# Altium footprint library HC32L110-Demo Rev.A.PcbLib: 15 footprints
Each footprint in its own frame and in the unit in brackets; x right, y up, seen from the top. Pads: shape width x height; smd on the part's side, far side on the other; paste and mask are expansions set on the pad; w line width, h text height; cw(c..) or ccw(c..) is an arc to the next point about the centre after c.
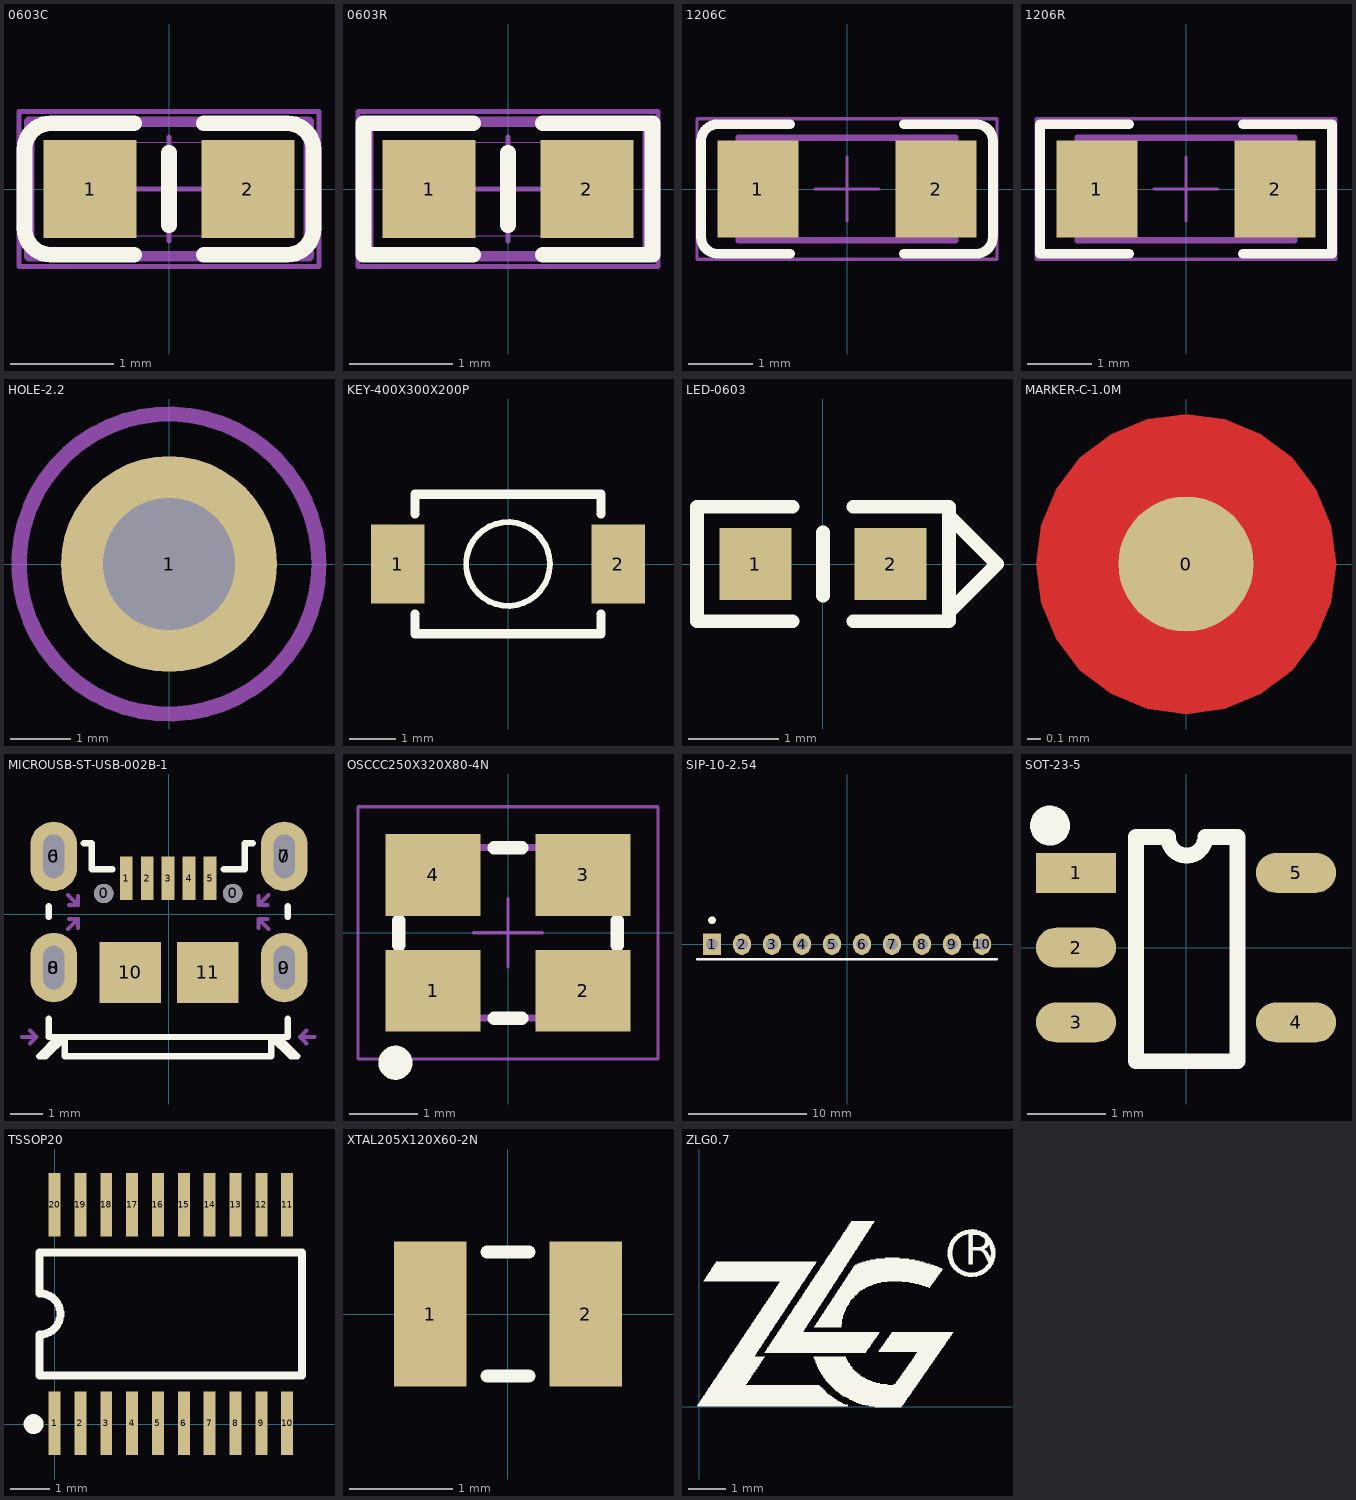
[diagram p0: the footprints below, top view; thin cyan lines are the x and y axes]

## 0603C [mm]
height 8.6
pads (2):
  rect 0.9x0.95 smd: 1(-0.762,0) 2(0.762,0)
Top Overlay:
  lines w0.152: -0.337,-0.635 -1.143,-0.635 cw(c-1.143,-0.381) -1.397,-0.381 -1.397,0.381 cw(c-1.143,0.381) -1.143,0.635 -0.337,0.635 ; 0,-0.35 0,0.35 ; 0.337,-0.635 1.143,-0.635 ccw(c1.143,-0.381) 1.397,-0.381 1.397,0.381 ccw(c1.143,0.381) 1.143,0.635 0.337,0.635
Mechanical 15:
  lines w0.1: -1.35,-0.65 -1.35,0.65 1.35,0.65 1.35,-0.65 -1.35,-0.65
Mechanical 16:
  lines w0.001: -0.85,-0.45 -0.85,0.45 0.85,0.45 0.85,-0.45 -0.85,-0.45
  lines w0.05: -0.5,0 0.5,0 ; 0,-0.5 0,0.5 ; -1.45,-0.75 -1.45,0.75 1.45,0.75 1.45,-0.75 -1.45,-0.75
3D body: height 0.3, standoff 0, extent -0.789,-0.381 0.811,0.419

## 0603R [mm]
height 8.6
pads (2):
  rect 0.9x0.95 smd: 1(-0.762,0) 2(0.762,0)
Top Overlay:
  lines w0.152: -0.337,-0.635 -1.397,-0.635 -1.397,0.635 -0.337,0.635 ; 0,-0.35 0,0.35 ; 0.337,-0.635 1.397,-0.635 1.397,0.635 0.337,0.635
Mechanical 15:
  lines w0.1: -1.35,-0.65 1.35,-0.65 1.35,0.65 -1.35,0.65 -1.35,-0.65
Mechanical 16:
  lines w0.001: -0.85,-0.45 0.85,-0.45 0.85,0.45 -0.85,0.45 -0.85,-0.45
  lines w0.05: -0.5,0 0.5,0 ; 0,-0.5 0,0.5 ; -1.45,-0.75 1.45,-0.75 1.45,0.75 -1.45,0.75 -1.45,-0.75
3D body: height 0.3, standoff 0, extent -0.8,-0.4 0.8,0.4

## 1206C [mil] "元件 长X宽=120X60mil"
height 40
pads (2):
  rect 50x60 smd: 1(-55,0) 2(55,0)
Top Overlay:
  lines w6: -90,29 cw(c-79.5,29.5) -80,40 -35,40 ; -90,30 -90,-30 ccw(c-79.5,-29.5) -79,-40 ; -80,-40 -35,-40 ; 35,-40 79,-40 ; 35,40 80,40 ; 79,40 cw(c79.5,29.5) 90,30 90,-29 cw(c79.5,-29.5) 80,-40
Mechanical 15:
  lines w3.94: -66.93,-31.5 -66.93,31.5 66.93,31.5 66.93,-31.5 -66.93,-31.5
Mechanical 16:
  lines w0.04: -66.93,-31.5 -66.93,31.5 66.93,31.5 66.93,-31.5 -66.93,-31.5
  lines w1.97: -19.68,0 19.68,0 ; 0,-19.68 0,19.68 ; -92.52,-43.31 -92.52,43.31 92.52,43.31 92.52,-43.31 -92.52,-43.31
3D body: height 39.37, standoff 0, extent -62,-32 63.98,30.99

## 1206R [mil] "元件 长X宽=120X60mil"
height 40
pads (2):
  rect 50x60 smd: 1(-55,0) 2(55,0)
Top Overlay:
  lines w6: -35,-40 -90,-40 -90,40 -35,40 ; 35,-40 90,-40 90,40 35,40
Mechanical 15:
  lines w3.94: -66.93,-31.5 66.93,-31.5 66.93,31.5 -66.93,31.5 -66.93,-31.5
Mechanical 16:
  lines w0.04: -66.93,-31.5 66.93,-31.5 66.93,31.5 -66.93,31.5 -66.93,-31.5
  lines w1.97: -19.68,0 19.68,0 ; 0,-19.68 0,19.68 ; -92.52,-43.31 92.52,-43.31 92.52,43.31 -92.52,43.31 -92.52,-43.31
3D body: height 23.62, standoff 0, extent -62.93,-31.5 63.06,31.5

## HOLE-2.2 [mm]
height 8.6
pads (1):
  round 3.6 hole 2.2: 1(0,0)
Mechanical 15:
  circle w0.254: c0,0 r2.5

## KEY-400X300X200P [mm]
height 8.6
pads (2):
  rect 1.15x1.7 smd: 1(-2.375,0) 2(2.375,0)
Top Overlay:
  circle w0.127: c0,0 r0.9
  lines w0.203: -2,-1.075 -2,-1.5 2,-1.5 2,-1.075 ; -2,1.075 -2,1.5 2,1.5 2,1.075

## LED-0603 [mm] "20100324  贴片0603LED   LSB"
height 0.889
pads (2):
  rect 0.8x0.8 smd: 1(-0.75,0) 2(0.75,0)
Top Overlay:
  lines w0.152: -0.337,-0.635 -1.397,-0.635 -1.397,0.635 -0.337,0.635 ; 0,-0.35 0,0.35 ; 0.337,-0.635 1.397,-0.635 1.397,0.635 0.337,0.635 ; 1.397,-0.533 1.93,0 1.397,0.533
3D body: height 0.3, standoff 0, extent -0.8,-0.4 0.8,0.4
3D body: height 0.4, standoff 0, extent -0.5,-0.403 0.5,0.403

## MARKER-C-1.0M [mm]
height 8.6
pads (1):
  round 1 smd paste-1.016 mask+0.5: 0(0,0)
Top Layer:
  pour cut-out: -1.109,0 -1.072,-0.287 -0.961,-0.555 -0.785,-0.785 -0.555,-0.961 -0.287,-1.072 0,-1.109 0.287,-1.072 0.555,-0.961 0.785,-0.785 0.961,-0.555 1.072,-0.287 1.109,0 1.072,0.287 0.961,0.555 0.785,0.785 0.555,0.961 0.287,1.072 0,1.109 -0.287,1.072 -0.555,0.961 -0.785,0.785 -0.961,0.555 -1.072,0.287

## MICROUSB-ST-USB-002B-1 [mm]
height 3
pads (17):
  oval 1.45x2.15 on Top Paste: 0(-3.575,-1.65) 0(-3.575,1.8) 0(3.575,-1.65) 0(3.575,1.8)
  round 0.6 hole 0.6 unplated: 0(-2.025,0.65) 0(1.975,0.65)
  rect 0.4x1.35 smd: 1(-1.325,1.115) 2(-0.675,1.115) 3(-0.025,1.115) 4(0.625,1.115) 5(1.275,1.115)
  oval 1.45x2.15 hole 0.65 slot 1.35 at 90 deg: 6(-3.575,1.8) 7(3.575,1.8) 8(-3.575,-1.65) 9(3.575,-1.65)
  rect 1.9x1.9 smd: 10(-1.2,-1.8) 11(1.2,-1.8)
Top Overlay:
  lines w0.2: -3.725,-3.234 -3.725,-3.8 3.675,-3.8 3.675,-3.234 ; -3.725,-0.081 -3.725,0.246 ; -3.425,-3.8 -4.025,-4.4 -3.825,-4.4 -3.225,-3.8 -3.225,-4.4 3.175,-4.4 3.175,-3.8 3.775,-4.4 3.975,-4.4 3.375,-3.8 ; -2.641,2.2 -2.4,2.2 -2.4,1.4 -1.752,1.4 ; 1.702,1.4 2.35,1.4 2.35,2.2 2.591,2.2 ; 3.675,-0.081 3.675,0.246
Mechanical 15:
  lines w0.127: -4.556,-3.8 -4.106,-3.8 ; -4.306,-4 -4.106,-3.8 ; -4.306,-3.6 -4.106,-3.8 ; -3.137,-0.455 -2.819,-0.137 ; -3.137,0.605 -2.819,0.287 ; -3.102,-0.137 -2.819,-0.137 ; -3.102,0.287 -2.819,0.287 ; -2.819,-0.42 -2.819,-0.137 ; -2.819,0.57 -2.819,0.287 ; 2.769,-0.42 2.769,-0.137 ; 2.769,0.57 2.769,0.287 ; 3.052,-0.137 2.769,-0.137 ; 3.052,0.287 2.769,0.287 ; 3.087,-0.455 2.769,-0.137 ; 3.087,0.605 2.769,0.287 ; 4.256,-4 4.056,-3.8 ; 4.256,-3.6 4.056,-3.8 ; 4.506,-3.8 4.056,-3.8
  text "PCB EDGE" at -1.905,-4.064 h0.89
  text "TopPaste" at -1.499,-0.412 h0.89

## OSCCC250X320X80-4N [mm]
height 0.8
pads (4):
  rect 1.4x1.2 smd: 1(-1.1,-0.85) 2(1.1,-0.85) 3(1.1,0.85) 4(-1.1,0.85)
Top Overlay:
  circle w0.25: c-1.651,-1.905 r0.125
  lines w0.2: -1.6,-0.178 -1.6,0.178 ; -0.203,-1.25 0.203,-1.25 ; -0.203,1.25 0.203,1.25 ; 1.6,-0.178 1.6,0.178
Mechanical 13:
  lines w0.1: -1.6,-1.15 -1.5,-1.25 ; -1.6,-1.05 -1.4,-1.25 ; -1.6,-0.95 -1.3,-1.25 ; -1.6,-0.85 -1.2,-1.25 ; -1.6,-0.75 -1.1,-1.25 ; -1.6,-0.65 -1,-1.25 ; -1.6,-0.55 -0.9,-1.25 ; -1.6,-0.45 -0.8,-1.25 ; -1.6,-0.35 -0.7,-1.25 ; -1.6,-0.25 -0.6,-1.25 ; -1.6,-1.25 1.6,-1.25 1.6,1.25 -1.6,1.25 -1.6,-1.25
Mechanical 15:
  lines w0.05: -0.5,0 0.5,0 ; 0,-0.5 0,0.5 ; -2.2,-1.85 2.2,-1.85 2.2,1.85 -2.2,1.85 -2.2,-1.85

## SIP-10-2.54 [mm]
height 8.6
pads (10):
  rect 1.5x1.8 hole 1: 1(-11.43,0)
  oval 1.5x1.8 hole 1: 2(-8.89,0) 3(-6.35,0) 4(-3.81,0) 5(-1.27,0) 6(1.27,0) 7(3.81,0) 8(6.35,0) 9(8.89,0) 10(11.43,0)
Top Overlay:
  circle w0.4: c-11.43,2.032 r0.125
  lines w0.2: -12.7,-1.27 12.7,-1.27
3D body: height 7.58, standoff -2.94, extent 10.16,-1.27 12.7,1.27
3D body: height 7.58, standoff -2.94, extent 2.54,-1.27 5.08,1.27
3D body: height 7.58, standoff -2.94, extent 0,-1.27 2.54,1.27
3D body: height 7.58, standoff -2.94, extent -2.54,-1.27 0,1.27
3D body: height 7.58, standoff -2.94, extent -5.08,-1.27 -2.54,1.27
3D body: height 7.58, standoff -2.94, extent -12.7,-1.27 -10.16,1.27
3D body: height 7.58, standoff -2.94, extent -10.16,-1.27 -7.62,1.27
3D body: height 7.58, standoff -2.94, extent -7.62,-1.27 -5.08,1.27
3D body: height 7.58, standoff -2.94, extent 5.08,-1.27 7.62,1.27
3D body: height 7.58, standoff -2.94, extent 7.62,-1.27 10.16,1.27

## SOT-23-5 [mil]
height 338.58
pads (5):
  rect 40x20 smd: 1(-55,37.4)
  oval 40x20 smd: 2(-55,0) 3(-55,-37.4) 4(55,-37.4) 5(55,37.4)
Top Overlay:
  circle w10: c-68,61 r5
  lines w7.87: -25,55.4 -25,-56.8 25.7,-56.8 25.7,55.4 ; -9,55.4 ccw(c0.35,55.4) 9.7,55.4
  lines w8: -25,55.4 -9,55.4 ; 9.7,55.4 25.7,55.4
3D body: height 42.79, standoff -0.51, extent -55.16,-57.06 55.09,57.09

## TSSOP20 [mm] "Shrink Small Outline; 20 Leads; Body Width 4.4 mm; Pitch 0.65 mm"
height 1.1
pads (20):
  rect 0.3x1.6 smd: 1(-0.004,0.019) 2(0.646,0.019) 3(1.296,0.019) 4(1.946,0.019) 5(2.596,0.019) 6(3.246,0.019) 7(3.896,0.019) 8(4.546,0.019) 9(5.196,0.019) 10(5.846,0.019) 11(5.846,5.519) 12(5.196,5.519) 13(4.546,5.519) 14(3.896,5.519) 15(3.246,5.519) 16(2.596,5.519) 17(1.946,5.519) 18(1.296,5.519) 19(0.646,5.519) 20(-0.004,5.519)
Top Overlay:
  circle w0.25: c-0.531,0 r0.125
  lines w0.2: -0.379,1.219 -0.379,2.249 ccw(c-0.379,2.769) -0.379,3.289 -0.379,4.319 6.221,4.319 6.221,1.219 -0.379,1.219

## XTAL205X120X60-2N [mm]
height 0.6
pads (2):
  rect 0.7x1.4 smd: 1(-0.75,0) 2(0.75,0)
Top Overlay:
  lines w0.127: -0.2,-0.6 0.2,-0.6 ; -0.2,0.6 0.2,0.6

## ZLG0.7 [mm] "7.8mmX5.6mm     不是太标准"
height 8.6
Top Overlay:
  drawing of 486 lines, arcs and shapes, not listed
  text "R" at 7.137,3.835 h0.89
